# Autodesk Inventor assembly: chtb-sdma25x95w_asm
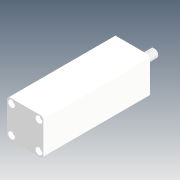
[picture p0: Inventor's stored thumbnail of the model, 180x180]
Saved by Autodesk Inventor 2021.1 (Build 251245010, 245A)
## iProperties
Company: Microsoft
Created: 2018-05
Part Number: chtb-sdma25x95w_asm
Description: STEP AP214
Document SubType Name: Assembly
Designer: user
Title: chtb-sdma25x95w_asm.STEP
Author: Windows
Revision Number: ÈÎºÎ
Sending System: SolidWorks 2015
Preprocessor: SwSTEP 2.0
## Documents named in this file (4)
- D:\Vault_2016\Projekty\Clamptek\Hydraulic\CHTB\CHTB-25\Inventor\chtb-sdma25x95w\chtb-sdma25x95w_asm.iam
- D:\Vault_2016\Projekty\Clamptek\Hydraulic\CHTB\CHTB-25\Inventor\chtb-sdma25x95w\CHTB-25QG.ipt
- D:\Vault_2016\Projekty\Clamptek\Hydraulic\CHTB\CHTB-25\Inventor\chtb-sdma25x95w\CHTB-SDMA25X95NBT.ipt
- D:\Vault_2016\Projekty\Clamptek\Hydraulic\CHTB\CHTB-25\Inventor\chtb-sdma25x95w\CHTB-SDMA25X95WHSG.ipt
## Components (3 placed, 3 different names)
1. CHTB-25QG_1
2. CHTB-SDMA25X95NBT_2
3. CHTB-SDMA25X95WHSG_3
